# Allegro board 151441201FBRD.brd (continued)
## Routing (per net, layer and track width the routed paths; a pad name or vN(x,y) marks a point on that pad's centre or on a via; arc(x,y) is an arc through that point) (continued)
PIN10: length 32.8
  TOP w0.102: U1.2 24.8,32.14 23.64,32.14 23.24,32.54 21.88,32.54 20.75,33.66 20.75,34.4 19.95,35.2 17.79,35.2 16.47,33.88 v1(16.47,33.55) ; J9.2 11.03,27.19 11.7,27.86 11.7,28.51 12.44,29.25 12.77,29.25 12.94,29.08 12.94,29.05 v1(13.12,28.87)
  TOP w0.381: v1(6.83,26.03) 6.83,26.45 7.57,27.19 J9.2
  BOTTOM w0.102: v1(13.12,28.87) 12.94,29.05 12.94,29.08 12.9,29.12 12.9,29.5 13.44,30.05 13.44,30.7 14.31,31.56 14.31,32.16 15.52,33.37 16.29,33.37 v1(16.47,33.55)
  BOTTOM w0.33: v1(6.83,26.03) 6.64,25.84 4.59,25.84 U19.3 4.59,26.64 4.1,27.12 Q10.6 3.65,27.46 3.48,27.62 3.48,28.22 3.24,28.45 Q10.3
PIN11: length 38.2
  TOP w0.102: U1.3 24.57,32.47 23.76,32.47 23.48,32.75 22,32.75 20.98,33.77 20.98,34.48 20.05,35.4 17.65,35.4 v1(15.99,33.75) ; v1(12.57,28.86) 12.53,28.9 12.39,28.9 11.99,28.5 11.99,27.85 11.36,27.22 11.36,26.98 10.97,26.59 10.97,25.24 10.38,24.65 J9.3
  TOP w0.381: J9.3 7.2,24.65 v1(6.84,24.29)
  BOTTOM w0.102: v1(15.99,33.75) 15.85,33.61 15.47,33.61 14.08,32.22 14.08,31.7 13.23,30.85 13.23,30.13 12.57,29.47 v1(12.57,28.86)
  BOTTOM w0.33: Q11.6 3.74,21.13 3.6,21.27 3.6,21.91 3.38,22.13 Q11.3 2.22,22.13 1.53,22.82 1.53,23.95 1.87,24.29 3.98,24.29 4.59,23.69 U19.4 4.59,23.44
  BOTTOM w0.381: v1(6.84,24.29) 6.56,24.01 6.56,23.86 6.14,23.44 4.59,23.44
PIN12: length 42.8
  TOP w0.102: v1(15.67,34.18) 16.06,34.18 17.49,35.61 20.15,35.61 21.18,34.58 21.18,33.89 22.09,32.99 23.66,32.99 23.87,32.78 24.32,32.78 U1.4 ; U1.4 24.65,33.12 U1.4 ; v1(12.38,28.39) 12.38,27.95 11.59,27.16 11.59,26.88 11.18,26.47 11.18,22.41 10.88,22.11 J9.4
  TOP w0.33: v1(3.48,19.49) 3.48,20.45 2.06,21.88 v1(2.06,23.48)
  TOP w0.381: v1(6.84,21.03) 6.84,21.85 7.09,22.11 J9.4
  BOTTOM w0.102: v1(15.67,34.18) 15.67,34.15 15.51,34 15.51,33.96 13.85,32.3 13.85,31.77 13.01,30.93 13.01,30.24 12.2,29.43 12.2,28.57 v1(12.38,28.39)
  BOTTOM w0.33: v1(6.84,21.03) 6.84,19.25 6.26,18.67 5.34,18.67 5.01,18.34 Q12.6 3.81,18.34 3.58,18.57 3.58,19.39 v1(3.48,19.49) 3.33,19.34 Q12.3
  BOTTOM w0.381: v1(2.06,23.48) 2.15,23.56 U19.6
PIN13: length 34
  TOP w0.102: 14.28,19.2 14.29,19.2 U20.1 ; 14.28,19.2 14.36,19.2 14.46,19.3 14.46,19.7 14.25,19.91 14.25,22.21 14.15,22.31 14.15,22.93 14.39,23.17 14.39,24.84 14.37,24.86 15.01,25.5 v1(15.01,26.03) ; 14.28,19.2 13.01,19.2 12.64,19.57 J9.5 ; U1.37 14.91,33.92 15.59,33.24 15.59,33.19 v1(16,32.78)
  TOP w0.381: J9.5 7.57,19.57 6.63,18.63 6.63,15.92 v1(6.45,15.73)
  BOTTOM w0.102: v1(15.01,26.03) 14.83,26.21 14.83,27.75 13.9,28.68 13.9,30.51 14.73,31.35 14.73,31.99 15.52,32.78 v1(16,32.78)
  BOTTOM w0.33: Q13.3 3.38,16.55 3.63,16.3 3.63,15.69 3.78,15.55 Q13.6 5.03,15.55 5.19,15.7 6.42,15.7 v1(6.45,15.73)
PIN14: length 38
  TOP w0.102: v1(15.98,32.25) 15.94,32.25 15.54,32.65 15.54,32.72 U1.38 ; v1(15.3,26.46) 15.38,26.38 15.38,25.57 14.59,24.78 14.59,23.05 14.39,22.84 14.39,22.41 14.46,22.34 14.46,20 14.71,19.74 14.71,18.14 13.85,17.28 12.44,17.28 12.24,17.48 12.24,18.01 12.38,18.16 U20.3 11.73,18.61 11.52,18.4 11.52,17.35 11.2,17.03 J9.6
  TOP w0.33: 6.79,15.14 7.09,15.44 7.09,16.64 7.48,17.03
  TOP w0.381: 6.79,15.14 6.79,14.57 6.03,13.81 v1(6.03,12.81) ; J9.6 7.48,17.03
  BOTTOM w0.102: v1(15.3,26.46) 15.12,26.64 15.12,27.78 14.12,28.78 14.12,30.39 14.94,31.21 14.94,31.9 15.52,32.49 15.74,32.49 v1(15.98,32.25)
  BOTTOM w0.33: Q14.3 3.44,13.75 3.61,13.58 3.61,12.99 3.86,12.75 Q14.6 5.97,12.75 v1(6.03,12.81)
PIN15: length 37.5
  TOP w0.102: J9.7 11.43,14.49 12.38,15.44 U20.4 12.38,16.66 12.55,16.82 14.15,16.82 15.13,17.81 15.13,23.09 14.81,23.41 14.81,24.7 15.66,25.56 15.66,26.74 v1(15.89,26.96) ; U1.39 15.36,32.34 15.36,32.17 v1(15.54,31.99)
  TOP w0.33: J9.7 7.39,14.49 6.56,13.65 6.56,12.57 6.24,12.25 v1(6.24,11.88)
  BOTTOM w0.102: v1(15.89,26.96) 15.89,27.64 14.56,28.97 14.56,30.22 15.68,31.33 15.68,31.88 15.57,31.99 v1(15.54,31.99)
  BOTTOM w0.33: v1(6.24,11.88) 6.7,11.42 6.7,10.44 6.26,10.01 5.29,10.01 5.24,9.96 Q15.6 3.81,9.96 3.58,10.18 3.58,10.82 3.44,10.96 Q15.3
PIN16: length 40.3
  TOP w0.102: v1(16.05,26.48) 16.05,25.61 15.03,24.59 15.03,23.55 15.34,23.24 15.34,17.71 14.29,16.66 U20.6 14.29,15.74 13.07,14.53 13.07,12.54 12.48,11.95 J9.8 ; v1(15.31,31.53) 14.9,31.94 14.9,32.23 U1.40
  TOP w0.381: J9.8 7.02,11.95 6.41,11.34 6.1,11.34 5.67,10.91 5.67,10.1 6.25,9.53 v1(6.25,7.4)
  BOTTOM w0.102: v1(15.31,31.53) 15.31,31.28 14.33,30.3 14.33,28.89 15.52,27.7 15.52,26.76 15.79,26.48 v1(16.05,26.48)
  BOTTOM w0.33: Q16.3 3.49,8.16 3.58,8.07 3.58,7.39 3.81,7.16 Q16.6 6.01,7.16 v1(6.25,7.4)
PWR_EN1: length 17
  TOP w0.102: v1(38.89,11.96) 37.84,13.01 37.84,17.16 36.99,18.01 34.26,18.01 33.94,17.69 31.34,17.69 30.82,18.21 v1(30.82,18.46)
  BOTTOM w0.102: Q1.5 38.78,12.46 38.8,12.49 R90.2 39.12,12.19 v1(38.89,11.96) ; U13.4 30.89,18.78 30.82,18.71 v1(30.82,18.46)
PWR_EN2: length 14.4
  TOP w0.102: v1(38.73,14.6) 38.14,15.19 38.14,17.55 37.48,18.22 34.04,18.22 33.75,17.93 31.63,17.93 31.34,18.22 v1(31.34,18.47)
  BOTTOM w0.102: Q2.5 38.78,15.26 38.8,15.28 R84.2 39.12,14.91 38.99,14.78 38.91,14.78 v1(38.73,14.6) ; v1(31.34,18.47) 31.54,18.67 U13.5
PWR_EN3: length 11.2
  TOP w0.102: v1(39.12,17.5) 38.18,18.43 33.85,18.43 33.56,18.14 32.29,18.14 v1(31.94,18.48)
  BOTTOM w0.102: U13.6 32.19,18.73 v1(31.94,18.48) ; Q3.5 38.78,18.05 38.8,18.08 R85.2 v1(39.12,17.5)
PWR_EN4: length 10.5
  TOP w0.102: v1(32.63,18.57) 33.6,18.57 33.68,18.66 37.57,18.66 38.75,19.84 v1(38.75,20.26)
  BOTTOM w0.102: v1(38.75,20.26) 39.12,20.63 R86.2 38.8,20.87 38.78,20.85 Q4.5 ; U13.7 32.84,18.79 v1(32.63,18.57)
PWR_EN5: length 14.1
  TOP w0.102: v1(31.43,28.47) 31.64,28.26 35.31,28.26 38.24,25.33 38.24,23.6 v1(38.76,23.08)
  BOTTOM w0.102: U14.4 31.46,28.75 31.43,28.72 v1(31.43,28.47) ; v1(38.76,23.08) 39.12,23.44 R92.2 38.8,23.66 38.78,23.64 Q5.5
PWR_EN6: length 11.1
  TOP w0.102: v1(32.11,28.62) 32.36,28.62 32.52,28.47 35.47,28.47 38.05,25.89 v1(38.81,25.89)
  BOTTOM w0.102: v1(38.81,25.89) 39.12,26.2 R93.2 38.58,26.46 38.55,26.43 Q6.5 ; U14.5 v1(32.11,28.62)
PWR_EN7: length 4.4
  BOTTOM w0.102: U14.6 32.76,30.36 33.64,31.25 33.64,31.71 33.53,31.83 R94.2 33.21,32.3 33.19,32.28 Q7.5
PWR_EN8: length 12
  TOP w0.102: v1(38.86,32.2) 38.86,31.36 36.17,28.67 35.17,28.67 34.66,29.18 v1(34.66,29.77)
  BOTTOM w0.102: v1(38.86,32.2) R95.2 38.55,32.81 38.52,32.78 Q8.5 ; v1(34.66,29.77) 34.45,29.56 34.45,28.92 34.26,28.73 33.54,28.73 33.41,28.86 U14.7
PWR_EN9: length 7.7
  TOP w0.102: v1(5.94,30.2) 6.21,30.2 6.37,30.36 8.41,30.36 8.54,30.48 v1(8.79,30.48)
  BOTTOM w0.102: v1(8.79,30.48) 8.79,31.11 9.35,31.67 9.58,31.67 9.71,31.8 U17.4 ; Q9.5 5.08,30.75 5.21,30.62 R101.2 5.75,30.43 5.75,30.4 v1(5.94,30.2)
PWR_EN10: length 13.8
  TOP w0.102: v1(9.59,31.29) 9.34,31.29 9.26,31.36 8.24,31.36 7.76,30.88 6.93,30.88 6.51,31.3 5.02,31.3 4.24,30.52 4.24,28.54 5.17,27.61 v1(5.17,27.3)
  BOTTOM w0.102: v1(9.59,31.29) 9.88,31.29 10.36,31.77 U17.5 ; Q10.5 5.14,27.96 5.27,27.83 R102.2 5.56,27.55 5.31,27.3 v1(5.17,27.3)
PWR_EN11: length 21
  TOP w0.102: v1(5.26,21.22) 5.26,22.58 4.7,23.14 4.7,25.57 5.53,26.4 5.53,27.61 4.51,28.63 4.51,30.35 5.25,31.09 6.35,31.09 6.82,30.62 8.08,30.62 8.38,30.92 v1(9.21,30.92)
  BOTTOM w0.102: v1(9.21,30.92) 10.22,30.92 11.01,31.7 U17.6 ; Q11.5 5.15,21.63 5.43,21.91 R103.2 5.66,21.61 v1(5.26,21.22)
PWR_EN12: length 20.9
  TOP w0.102: v1(6.37,20.52) 6.45,20.61 6.45,22.82 5.66,23.61 5.66,25.11 6.45,25.91 6.45,27.66 6.74,27.95 10.83,27.95 v1(11.2,28.32)
  BOTTOM w0.102: U17.7 11.66,32.03 11.26,31.64 11.26,28.38 v1(11.2,28.32) ; v1(6.37,20.52) 6.37,19.47 6.02,19.12 R104.2 4.99,19.12 4.71,18.84 Q12.5
PWR_EN13: length 7.4
  BOTTOM w0.102: Q13.5 4.99,16.05 5.22,16.28 R109.2 5.73,16.28 6.06,16.61 9.08,16.61 10.09,15.6 U18.4
PWR_EN14: length 8.8
  TOP w0.102: v1(7.06,12.74) 10.45,12.74 10.53,12.81 v1(10.78,12.81)
  BOTTOM w0.102: v1(7.06,12.74) 6.52,13.28 R110.2 5.34,13.28 5.31,13.25 Q14.5 ; v1(10.78,12.81) 10.78,13.07 10.74,13.11 U18.5
PWR_EN15: length 11
  TOP w0.102: v1(10.87,10.76) 10.84,10.74 v1(6.2,10.74)
  BOTTOM w0.102: Q15.5 5.38,10.46 R111.2 v1(6.2,10.74) ; U18.6 11.39,12.25 10.87,11.72 v1(10.87,10.76)
PWR_EN16: length 13.5
  TOP w0.102: v1(11.7,10.63) 11.7,9.7 10.57,8.57 7.42,8.57 v1(6.78,7.93)
  BOTTOM w0.102: Q16.5 5.38,7.66 R112.2 6.41,7.94 6.42,7.93 v1(6.78,7.93) ; U18.7 12.04,12.19 11.7,11.85 v1(11.7,10.63)
QSPI_CLK: length 9.3
  TOP w0.254: U1.53 14.47,28.59 13.85,27.97 v1(13.76,27.97)
  BOTTOM w0.254: U2.6 9.53,24.14 9.61,24.14 10.19,24.72 10.84,24.72 11.78,25.66 13.23,25.66 14.02,26.45 14.02,27.72 v1(13.76,27.97)
QSPI_D0: length 10
  TOP w0.254: v1(13.43,27.56) 13.46,27.53 13.97,27.53 14.52,28.08 U1.54
  BOTTOM w0.254: U2.5 8.26,24.04 9.35,25.13 10.57,25.13 11.46,26.02 12.85,26.02 13.43,26.6 v1(13.43,27.56)
QSPI_D1: length 16.9
  TOP w0.254: U1.55 13.02,26.01 13.02,24.73 12.4,24.11 12.4,21.58 v1(12.75,21.23)
  BOTTOM w0.203: R121.1 13.07,16.65 12.86,16.45 11.25,16.45 10.8,16.9 U2.2
  BOTTOM w0.254: R121.1 13.07,17.1 13.09,17.12 13.09,17.93 12.94,18.07 12.94,20.13 13.22,20.4 13.22,20.76 v1(12.75,21.23)
QSPI_D2: length 18.2
  TOP w0.254: v1(13.38,19.88) 13.44,19.95 R6.2 13.44,21.18 12.81,21.81 12.81,24.01 13.44,24.64 13.44,25.87 U1.56
  BOTTOM w0.203: U2.3 9.53,17.44 10.83,16.14 13.16,16.14 13.56,16.55
  BOTTOM w0.254: v1(13.38,19.88) 13.45,19.81 13.45,17.45 13.56,17.33 13.56,16.55
QSPI_D3: length 7.9
  TOP w0.254: U1.57 14.22,26.08 v1(14.22,25.97) 14.09,25.84 R7.2
  BOTTOM w0.254: U2.7 10.8,24.05 12.06,25.3 13.55,25.3 v1(14.22,25.97)
QSPI_SSN: length 13.3
  TOP w0.254: U1.52 14.09,28.78 13.94,28.78 12.33,27.17 R5.2 12.33,26.41 11.92,26 11.92,21.41 v1(12.73,20.61)
  BOTTOM w0.254: v1(12.73,20.61) 12.56,20.43 12.56,18.47 12.07,17.99 U2.1
RESETN: length 41.9
  TOP w0.102: R4.2 11.17,31.87 11.24,31.8 11.24,30.69 11.51,30.42 C95.1 ; C95.1 11.69,29.96 v1(11.66,29.93) ; C95.1 11.84,30.42 12.04,30.61 12.04,30.69 U1.45 ; v1(13.28,22) 13.1,22.18 13.1,23.67 v1(13.39,23.96) ; S1.2 S1.1 11.06,7.16 14,10.11 v1(14,13.98)
  BOTTOM w0.102: v1(14,13.98) 13.65,14.34 13.65,14.83 13.86,15.05 13.86,18.91 13.73,19.05 13.73,20.12 13.51,20.34 13.51,21.07 13.28,21.3 v1(13.28,22) ; v1(13.39,23.96) 13.39,24.59 14.62,25.81 14.62,26.14 14.52,26.24 14.52,27.73 13.87,28.37 13.57,28.37 13.21,28.01 12.17,28.01 11.97,28.21 11.97,29.61 v1(11.66,29.93)
RF_TX-RX: length 2.8
  TOP w0.203: 20.47,38.57 20.47,38.56 U1.21
  TOP w0.254: C12.2 21.84,39.25
  TOP w0.584: 21.84,39.25 21.56,39.25 arc(21.19,39.18) 20.87,38.97 20.47,38.57
STR1: length 37.8
  TOP w0.102: U1.14 22.46,36.59 23.57,36.59 v1(23.75,36.41) ; v1(29.92,28.17) 30.26,27.83 34.13,27.83 35.64,26.31 35.64,24.12 35.23,23.71 30.41,23.71 v1(29.52,22.82)
  BOTTOM w0.102: v1(29.92,28.17) 29.51,28.58 U14.1 29.51,30.36 29.27,30.6 28.56,30.6 28.45,30.49 27.72,30.49 27.49,30.72 27.49,35.67 27.16,36.01 27.16,36.36 27.67,36.88 27.67,37.45 27.22,37.9 25.88,37.9 25.11,37.12 25.11,36.61 24.81,36.31 23.84,36.31 v1(23.75,36.41) ; v1(29.52,22.82) 29.57,22.77 29.57,21.27 28.94,20.64 U13.1
STR2: length 40.4
  TOP w0.102: v1(1.96,15.44) 1.06,16.33 1.06,27.08 3.12,29.14 3.12,29.98 4.7,31.56 6.78,31.56 7.03,31.31 v1(7.57,31.31) ; U1.35 14.81,35.15 12.96,35.15 12.67,35.44 11.75,35.44 v1(11.35,35.84)
  BOTTOM w0.102: v1(1.96,15.44) 2.14,15.26 2.14,15.13 2.55,14.71 4.81,14.71 5.46,15.36 7.04,15.36 7.46,15.78 7.95,15.78 8.14,15.6 U18.1 ; v1(7.57,31.31) 7.75,31.49 7.75,31.74 7.76,31.75 U17.1 7.76,33.75 9.09,35.08 11.14,35.08 11.35,35.29 v1(11.35,35.84)
USB_DM: length 18.8
  TOP w0.203: U1.65 17.81,25.14 17.81,25.11
  TOP w0.3: 19.21,12.03 19.21,11.76 19.63,11.34 19.63,10.68 19.74,10.57 CM2.6 ; 19.21,12.03 19.21,14.54 16.73,17.03 16.73,17.84 17.13,18.24 17.13,19.01 16.73,19.42 16.73,24.03 17.81,25.11 ; 19.21,12.03 19.22,12.04 U8.4
USB_DP: length 18.8
  TOP w0.203: U1.64 17.52,25.42 17.5,25.42
  TOP w0.3: 18.77,12.04 18.77,12.04 U8.3 ; 18.77,12.04 18.77,14.36 16.29,16.84 16.29,24.22 17.5,25.42 ; 18.77,12.04 18.77,11.57 19.19,11.16 19.19,10.68 19.09,10.58 CM2.5
USB_DRVBUS: length 25.2
  TOP w0.102: v1(14.09,19.56) 14.01,19.48 13.14,19.48 11.39,21.23 11.39,26.38 11.88,26.87 11.88,27.13 13.68,28.92 13.68,29.5 U1.50 ; v1(14.01,14.58) 14.37,14.23 14.37,13.54 14.32,13.54 14.22,13.43 14.22,9.75 13.21,8.75 R120.2
  BOTTOM w0.102: v1(14.09,19.56) 14.09,14.91 14.01,14.84 v1(14.01,14.58)
USB_ID: length 20.4
  TOP w0.102: CM2.4 18.44,10.63 17.69,11.39 16.98,11.39 16.29,12.07 16.29,13.54 16.69,13.94 U8.1 17.64,14.24 17.64,14.8 16.83,15.62 16.6,15.62 v1(16.42,15.8) ; U1.62 17.03,26.06 17.03,25.9 15.65,24.53 v1(15.65,23.83)
  BOTTOM w0.102: v1(15.65,23.83) 15.65,23.58 15.71,23.52 15.71,16.51 v1(16.42,15.8)
USB_OTG_POWER_FAULT: length 23.7
  TOP w0.102: v1(19.23,26.35) 19.97,27.09 20.6,27.09 U1.72 ; U1.72 20.98,26.72 U1.72 ; R119.2 14.22,8.84 14.42,9.04 14.42,13.26 14.72,13.56 14.72,13.56 14.72,14.73 v1(15.57,15.58)
  BOTTOM w0.102: v1(15.57,15.58) 15.57,15.84 15.51,15.9 15.51,23.41 15.24,23.67 15.24,23.98 15.5,24.23 15.69,24.23 17.69,26.23 18.15,26.23 18.3,26.08 18.96,26.08 v1(19.23,26.35)
VSYS_IN: length 5.4
  BOTTOM w0.102: J2.2 29.44,2.69 29.61,2.86 29.64,2.86 TP1.1
  BOTTOM w0.5: J2.2 27.96,3.37 R60.2
WAKEUP0: length 58.9
  TOP w0.102: v1(26.87,24.38) 24.52,26.73 v1(23.95,26.73) ; v1(28.58,12.89) 28.58,12.48 29.83,11.23 35.08,11.23 37.27,9.03 S2.1 S2.2 37.96,2.64 v1(38.18,2.43) 38.05,2.31 R54.2 ; v1(27.88,19.76) 28.06,19.58 28.06,16.36 28.11,16.31 v1(28.11,16.05) ; v1(12.35,30.44) U1.46
  BOTTOM w0.102: v1(38.18,2.43) 38.06,2.31 C94.1 ; v1(28.11,16.05) 28.03,15.97 28.03,14.51 28.58,13.96 v1(28.58,12.89) ; v1(12.35,30.44) 12.35,30.72 12.36,30.73 12.36,30.93 12.7,31.27 12.7,33.62 12.51,33.81 12.51,34.91 12.97,35.36 12.97,36.59 13.49,37.11 14.67,37.11 16.59,35.19 17,35.19 21.48,30.71 21.48,29.98 22.68,28.77 22.68,28 v1(23.95,26.73) ; v1(26.87,24.38) 27.34,23.91 27.34,23.24 27.88,22.7 v1(27.88,19.76)
XTAL_IN: length 3
  TOP w0.152: Y1.1 16.53,39.49 16.78,39.24 16.78,38.27 U1.26
XTAL_OUT: length 3.2
  TOP w0.152: Y1.3 15.1,38.26 15.86,37.5 16.99,37.5 U1.27
N04866: length 6.9
  TOP w0.178: 12.47,32.98 12.88,32.57 U1.43
  TOP w0.254: L3.1 10.64,36.68 10.13,36.17 10.13,34.9 10.51,34.53 11.88,34.53 12.23,34.18 12.23,33.22 12.47,32.98
N14504: length 1.7
  TOP w0.254: FL1.1 24.05,39.25 ; 22.86,39.25 C12.1
  TOP w0.584: 24.05,39.25 22.86,39.25
N14557: length 3.3
  TOP w0.584: L1.1 32.72,39.25 ; 32.72,39.25 L2.1 32.72,39.25 ; 32.72,39.25 ANT1.1
N16809573: length 1.4
  BOTTOM w0.102: D10.4 38.52,5.85 38.42,5.74 R49.1
N16809863: length 6.2
  TOP w0.102: v1(38.39,7.92) 38.39,7.66 38.32,7.6 v1(38.32,5.23)
  BOTTOM w0.102: R118.1 37.96,9.42 38.39,8.99 v1(38.39,7.92) ; D10.1 39.05,4.75 38.57,5.23 v1(38.32,5.23)
N16809865: length 1.5
  BOTTOM w0.102: D10.3 38.52,6.65 38.16,7.01 R48.1
N16909824: length 1.9
  TOP w0.102: J11.1 14.22,6.23 R119.1
N16909825: length 2
  TOP w0.102: 12.7,5.98 12.7,6.04 13.21,6.55 R120.1
N16943358: length 5.3
  TOP w0.254: 25.64,39.25 FL1.3
  TOP w0.584: 29.67,39.25 L1.2 ; 29.67,39.25 L5.1 29.67,39.25 ; 29.67,39.25 25.64,39.25

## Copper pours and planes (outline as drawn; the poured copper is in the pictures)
GND on TOP: 25.24,17.34 25.23,17.04 25.22,17.02 25.47,16.77 26.5,16.77 26.7,16.96 26.7,17.97 24.67,20 24.32,20 23.91,19.6 23.91,18.52 24.02,18.41
GND on TOP: 0.4,34.04 2.4,34.04 2.85,33.59 2.85,31.64 3.71,30.78 3.71,29.35 3.36,29 2.71,29 2.41,29.31 1.25,29.31 0.26,30.3 0.26,33.9
GND on TOP: 20.19,41.54 32.94,41.56 32.94,38.26 32.99,35.8 32.69,35.49 30.45,35.49 30.23,35.72 30.23,37.63 30.07,37.78 24.43,37.78 24.03,37.4 21.62,37.4 20.65,38.36 20.45,38.36 20.12,38.06 19.61,38.55 19.61,40.8
GND on TOP: 6.33,25.52 6.83,25.52 7,25.35 7,23.98 7.2,23.78 7.72,23.78 7.89,23.61 7.89,22.78 7.77,22.66 6.92,22.66 6.05,23.54 6.05,23.58 5.85,23.78 5.85,25.03 6.33,25.51
GND on TOP: 28.15,24.96 26.04,27.07 26.04,28.56 26.19,28.71 27.62,28.71 27.85,28.47 27.85,27.58 28.31,27.12 29.17,27.12 29.82,26.47 33.88,26.47 33.95,26.54 34.97,26.54 35.24,26.28 35.24,24.96 35.07,24.79 34.76,24.79 34.46,25.09 34.1,25.09 33.92,25.28 29.26,25.28 28.95,24.96
GND on TOP: 14.5,14.66 17.15,15.99 16.4,13.85 17.64,9.78 15.5,7.45 14.44,8.43
GND on TOP: 32.09,15.52 34.1,15.52 34.77,16.18 36.45,16.18 36.62,16.35 36.62,16.95 36.51,17.06 34.31,17.06 33.64,16.39 32.04,16.39 31.96,16.31 31.96,15.64
GND on TOP: 11.97,36.19 11.97,35.64 12,35.61 13.01,35.42 13.09,35.32 13.98,35.32 14.03,35.45 14.33,35.75 15.29,35.84 16.06,36.51 16.02,36.73 15.8,36.81 15.78,36.84 15.56,36.84 15.4,36.67 15.4,36.6 15.34,36.54 13.83,36.54 13.59,36.3 13.59,36.22 12.35,36.22 12.33,36.24 12.02,36.24
GND on TOP: 34.76,22.41 37.62,22.41 37.94,22.09 37.94,20 37.02,18.87 33.97,18.87 33.78,19.03 34.3,19.77 34.32,21.94
GND on TOP: 35.06,17.04 36.72,17.04 37.39,16.37 37.39,13.04 38.7,11.73 40.04,11.73 40.26,11.52 40.26,8.5 40.15,8.39 39.13,8.39 39.01,8.5 39.01,9.89 37.04,11.86 34.81,11.86 34.69,11.98 34.69,14.23 34.69,14.23 34.69,16.67
GND on TOP: 18.9,33.64 19.05,33.64 19.94,34.5 19.68,34.83 18.36,34.83 18.07,34.46
GND on TOP: 26.71,21.11 27.65,21.11 29.34,19.42 29.34,16.14 29.14,15.95 28.53,15.95 28.26,16.22 28.26,19.46 27.77,19.95 26.54,19.95 26.15,20.34 26.15,20.74 26.52,21.11 26.7,21.11
GND on TOP: 0.29,13.81 0.74,14.25 1.84,14.25 2.25,14.67 2.25,15.48 1.3,16.43 1.3,19.58 1.35,19.63 1.35,27.51 1.91,28.07 3.97,28.07 5.3,26.74 5.3,26.45 4.44,25.6 4.44,23 5,22.44 5,14.85 4.87,14.71 4.87,13.23 4.68,13.05 4.69,13.04 4.69,9.46 4.4,9.18 4.4,7.17 5.13,6.44 10.31,6.44 10.69,6.07 10.69,4.36 10.36,4.03 0.78,4.03 0.29,4.51
GND on BOTTOM: 25.53,6.5 23.21,8.55 21.91,9.74 20.4,9.74 16.23,9.71 15.12,6.68 15.12,0.73 14.76,0.36 3.24,0.36 0.31,3.3 0.31,38.69 3.23,41.62 6.11,41.62 6.57,41.28 6.57,39.4 9.92,39.41 9.9,41.26 10.2,41.62 18.61,41.62 18.61,41.62 32.98,41.62 32.98,34.63 40.47,34.65 40.46,8.86 40.24,8.41 38.87,8.38 38.87,5.27 40,5.27 40,2.75 37.76,0.51 26.38,0.5 26.47,0.57 26.45,0.68 25.66,1.46 25.56,1.48 25.49,1.39 25.49,1.03 26.01,0.5 26.01,0.5 25.49,1.03 25.49,2.87 25.53,2.91 ; 24 cut-outs
GND on BOTTOM: 12.18,33.02 13.13,33.02 13.17,33.06 13.39,32.84 13.39,30.56 13.11,30.28 11.75,30.28 11.75,32.6
V1P8 on TOP: 17.58,36.56 17.43,36.41 17.43,36.3 17.42,36.23 17.55,36.08 17.72,36.04 20.28,36.04 20.28,36.69 18.97,38 18.97,41.13 18.53,41.57 10.78,41.57 10.5,41.3 10.5,38.41 10.76,38.16 11.69,38.16 11.99,38.45 11.99,39.68 12.15,39.84 13.57,39.84 14.35,40.62 15.96,40.62 15.97,40.61 16.33,40.61 17.15,39.79 17.15,38.32 18.21,37.25 18.21,37 17.77,36.56
V1P8 on BOTTOM: 21.23,36.15 21.16,36.03 20.14,36.03 19.99,36.18 19.99,36.76 20.07,36.89 20.5,36.89
V1P8 on BOTTOM: 18.62,37.27 18.8,37.09 18.8,36.23 18.59,36.03 18.57,36.03 18.41,36.18 17.98,36.18 17.6,36.56 17.6,36.59 18.29,37.27
V3P3 on TOP (solid shape): 22.8,18.03 22.8,17.03 22.8,15.6 21.94,14.74 21.14,14.73 20.38,14.73 20.28,14.83 20.28,17.55 20.36,17.63 21.1,17.63 21.2,17.73 21.73,17.73 22.13,18.13 22.7,18.13
V3P3 on TOP: 13.55,23.87 14.05,23.87 14.18,23.74 14.18,23.5 14,23.32 14,22.27 14.15,22.12 14.15,21.19 14.02,21.06 13.75,21.06 13.51,21.3 13.51,22.07 13.29,22.29 13.29,23.61
V3P3 on TOP: 19.48,26.63 19.02,27.09 18.7,27.09 18.28,26.67 17.89,26.67 17.33,27.23 15.06,29.5 15.06,29.58 13.06,31.59 12.5,31.59 11.66,32.44 11.13,32.44 11.07,32.38 11.07,32.03 11.02,31.98 10.54,31.98 10.54,32.94 10.86,33.26 11.97,33.26 13.03,32.2 13.4,32.2 13.79,32.59 14.13,32.59 15.08,31.64 15.74,31.64 16.15,31.22 16.19,31.22 18.72,28.69 19.3,28.69 22.38,31.77 23.49,31.77 23.65,31.61 24.17,31.61 24.43,31.35 24.43,30.94 20.13,26.63
V3P3 on TOP: 23.98,10.67 23.97,12.99 22.8,14.17 22.8,15.64 22.76,15.6 21.79,15.6 21.15,14.96 21.15,13.72 22.14,12.64 22.1,10.83 22.11,10.83 22.33,10.46 23.77,10.46
V3P3 on TOP: 25.98,29.51 25.98,31.02 25.68,31.33 25.68,32.06 25.98,32.36 25.98,32.64 24.75,33.87 24.75,34.02 24.99,34.26 25.68,34.26 25.68,34.64 25.72,34.68 26.85,34.68 27.06,34.46 27.06,34.19 27.16,34.09 27.16,29.9 26.7,29.43 26.06,29.43
V3P3 on BOTTOM: 25.35,34.22 23.55,34.22 22.83,34.83 23.72,35.82 25.1,35.85 25.37,35.57 25.37,34.25
V3P3 on BOTTOM: 23.42,31.53 23.99,31.53 24.27,31.81 24.79,31.81 25.08,31.52 25.77,31.52 25.9,31.65 25.9,32.12 26.08,32.3 26.78,32.3 26.9,32.18 26.9,31.27 26.6,30.98 25.53,30.98 24.99,30.43 23.46,30.44 23.25,30.63 23.28,31.4
V3P3 on BOTTOM: 27.05,36.26 27.05,37.58 25.73,37.58 25.73,36.26
V3P3 on BOTTOM: 16.01,13.57 15.2,13.58 14.21,14.56 14.21,19.8 13.68,20.33 13.68,22.14 13.06,22.76 13.06,23.67 13.3,23.91 13.72,23.91 14.04,24.23 14.04,24.75 15.53,26.24 16.05,26.24 16.4,26.59 16.4,27.2 16.77,27.56 17.08,27.56 17.55,28.03 17.68,28.03 17.91,27.79 17.91,27.79 17.95,27.75 18.26,27.75 18.59,27.42 18.59,26.95 18.26,26.62 17.71,26.62 14.45,22.69 14.46,22.67 15.27,21.87 15.27,16.42 16,15.38
V3P3_OUT on TOP (solid shape): 24.06,18.14 25.02,17.19 25.03,16.73 25.7,16.06 25.7,13.93 25.13,13.36 24,13.36 23.12,14.24 23.12,14.95 23.42,15.25 23.42,18.06 23.5,18.14
V5P0_VIN on TOP (solid shape): 26.27,7.94 26.27,7 26.59,6.67 28.63,6.67 28.75,6.56 28.75,5.46 28.46,5.18 25.27,5.18 25.13,5.32 25.13,6.48 24.85,6.76 23.8,6.76 23.69,6.87 23.69,7.61 23.72,7.65 24.51,7.65 24.98,8.12 26.09,8.12
VCC_FLEX1 on TOP: 38.27,34.07 38.27,12.22 40.31,12.22 40.31,34.07
VDD18_F_86 on BOTTOM: 24.54,30.18 24.55,29.21 25.86,29.21 25.86,30.19
VDD33_20 on BOTTOM: 22.91,38.01 21.04,38.01 20.52,37.57 20.52,37.22 21.36,36.41 22.17,35.6 22.73,35.6 22.91,35.77
SW3P3 on TOP (solid shape): 27.06,12.4 27.06,11.51 26.81,11.26 25.84,11.26 25.58,11.01 25.58,9.65 25.54,9.61 24.96,9.61 24.89,9.68 24.89,11.75 26.26,13.12 26.34,13.12
VSYS_IN on TOP (solid shape): 30.18,6.44 30.18,2.69 30.18,2.68 30.18,1.43 29.86,1.11 28.39,1.11 27.98,1.53 27.98,4.17 28.45,4.64 28.92,4.64 29.39,5.11 29.39,6.63 29.43,6.68 29.94,6.68

Small or netless copper shapes (teardrops, artwork), in the pictures only: 18 on TOP, 26 on BOTTOM

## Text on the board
BOTTOM: BOTTOM
Ref Des/Silkscreen Bottom: A | K | VBUS_EN | FLAG | GROUND | VBUS | VSYS
TOP: TOP
Ref Des/Silkscreen Top: S/N: | ELEMENT-R4
DIMENSION: UNIT:mm | 41.92 | 14.52 | 3.9 | 0.85 | X4 | 2
DEVICE_TYPE_TOP: NAME: | DATE: | JOB: XXXXXXX | SHEET | REV: 2.0 | OF  10 | 11 AUGUST 2014 | RD-88MW302-QFN88 | VIEW "TOP SIDE"
FAB_DETAIL: (L2_BOTTOM) | (L1_TOP) | Bottom side solder mask(0.80mils) | Top side solder mask(0.80mils) | copper+plating | cpper+plating | Prepreg(23.00mils) | (2 OZ) | 2 LAYERS STACK-UP | Overall thickness 30 mils+/-10%
User.7: SOLDERMASK_TOP
User.8: SOLDERMASK_BOTTOM
User.10: SILKSCREEN_TOP
User.11: SILKSCREEN_BOTTOM
User.12: PASTE MASK TOP
User.13: PASTE MASK BOT
User.16: PWR
User.17: GND
User.18: 19. BOARD EDGES AROUND ANT1 MUST BE SMOOTH AND FREE OF BOARD BREAK-OUT BURRS | 20. Impedance control: | 11,WARP AND TWIST:  SHALL NOT EXCEED .125mm PER MM | 16. NO ADDITIONAL HOLES ON PCB | 17. Do not cover vias with soldermask in soldermask keepout areas | 18. REMOVE UNUSED PADS FROM INTERNAL LAYERS EXCEPT UNUSED PADS ON BOARD EDGES. | 12,PLACE VENDOR LOGO AND DATE CODE ON SOLDER SIDE IN SILKSCREEN. | 13,BARE BOARD ELECTRICAL TEST TO BE DONE WITH REFERENCE TO SUPPLIED | 14,VENDOR MAY USE TEAR-DROP OR OTHER SIMILAR METHOD TO ENSURE CONNECTIONS. | 15,ELECTRICAL TEST FOR OPENS AND SHORTS. | 10,FABRICATION TOLERANCES:  END PRODUCT LINE WIDTHS AND LANDS | 9,REGISTRATION: FRONT TO BACK TO BE WITHIN .075mm TRUE POSITION. | 8,ALL HOLES TO BE WITHIN +/-.125mm TRUE POSITION WITH planes | 7,ALL PTH HOLE DIAMETERS APPLY AFTER PLATING. TOL +/-.05mm. | 6,SILKSCREEN:GREEN NON-CONDUCTIVE EPOXY INK. NO SILKSCREEN ON COMPONENT PADS. | 5,IMPEDANCE CONTROL BOARD. SPECIFIED MATERIAL MUST BE USED.SEE IMPEDANCE CHART FOR DETAILS. | 4.Finish: | 2,REMOVE ALL BURRS AND SHARP EDGES. | 3,MATERIAL: LAMINATE/PREPREG FR4 OR EQUIVALENT. DK VALUE = 4.2 | FAB NOTES: | 1,FABRICATE PCB IN ACCORDANCE WITH IPC-6012 CLASS 2 OR MOST CURRENT REVISION. | SOLDERMASK OVER BARE COPPER (SMOBC) WITH LIQUID PHOTO IMAGINABLE (LPI) SOLDERMASK. | PRESERVE HOLE PADS ON START AND END LAYERS. | SHALL NOT VARY MORE THAN THE SMALLER OF .05mm OR 20% | ANNULAR RING SHALL BE .05mm ON EXTERNAL LAYERS . | OF THE TRACE WIDTH FROM THE MASTER PATTERN.   THE MINIMUM | 11.81/5.5 mils width/gap on top layer should be controlled 90 ohms +/- 10%. | Single ended signals: | 23 mils width on top layer should be controlled 50 ohms +/- 10% | Differential pairs: | THESE DETAILED NOTES MAY SUPERSEDE IPC REQUIREMENTS. USE MARVELL SUPPLIED ARTWORK. | COLOR WHITE PC401 OR EQUIVALENT. MAXIMUM THICKNESS .05mmds, | 2-10 MICROINCHES IMMERSION GOLD OVER 150-200 MICROINCHES NICKLE. | ALL COPPER NOT COVERED BY SOLDERMASK SHALL BE PLATED WITH | FAB_DWG
User.20: ASSY_TOP
User.21: ASSY_BOT
User.26: FIGURE | SIZE | 8.0 | 28.0 | 40.0 | 39.0 | 59.098 | 118.098 | 33.5x25.598 | 59.059x31.5 | FINISHED HOLE CHART | ALL UNITS ARE IN MILS | TOLERANCE | +3.0/-3.0 | +2.0/-2.0 | +5.0/-5.0 | PLATED | NON-PLATED | QTY | 433 | 2 | 3 | 1
